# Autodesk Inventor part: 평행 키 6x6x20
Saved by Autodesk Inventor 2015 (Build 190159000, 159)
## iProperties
Created: 2026-07
Part Number: 평행 키 6x6x20
Material: 일반
Document SubType Name: Modeling
Designer: user
Density: 1 g/cm^3
Appearance: 기본값
Author: user
Author: jhkim
Creation Date: 2026-07-01
Sending System: Autodesk Inventor 2027
Preprocessor: ST-DEVELOPER v20.1
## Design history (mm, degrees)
node "평행 키 6x6x201"
body "Solid1"
node "기준1"
